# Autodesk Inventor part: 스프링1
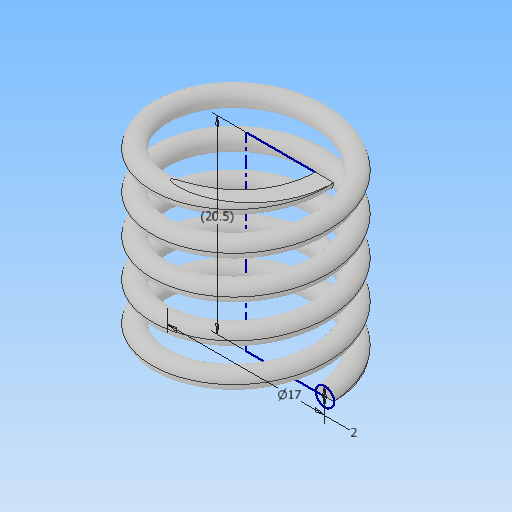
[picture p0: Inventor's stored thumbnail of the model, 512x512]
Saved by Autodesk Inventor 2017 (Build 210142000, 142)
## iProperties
Part Number: 스프링1
Material: 일반
Document SubType Name: Modeling
Designer: MRC
Density: 1 g/cm^3
Appearance: 기본값
Mass: 0.821961 g
Surface Area: 16.7185 cm^2
Volume: 0.821961 cm^3
Author: MRC
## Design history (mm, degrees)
sketch "스케치1"
  geometry: L1 (0, 0)-(0, 20.5); L2 (0, 0)-(8.5, 0); L3 (0, 20.5)-(7.5, 20.5); C1 r 1 at (8.5, 0)
  constraints: 6 end point, 2 horizontal, 1 centre point, 1 coincident, 1 vertical
  dimensions: "d0" = 20.5 distance of L1.start L1.end (derived); "d1" = 2 diameter of C1; "d2" = 17 diameter of L2.end L1
feature "코일1" sketch "스케치1" pitch "d3" = 10; turns "d5" = 5; dims "d4" = 20.5 (= d0), "d6" = 0, angle "d7" = 90 deg, angle "d8" = 90 deg, "d9" = 0, "d10" = 0
sketch "스케치2"
  geometry: L1 (20.5, 18.5)-(0, 18.5); L2 (0, 18.5)-(0, -18.5); L3 (0, -18.5)-(20.5, -18.5); L4 (20.5, -18.5)-(20.5, 18.5); 2 further points
  constraints: 8 end point, 2 parallel, 1 coincident, 1 horizontal, 1 midpoint, 1 perpendicular
  dimensions: "d11" = 37 distance of L3.end L1.start; "d12" = 20.5 distance of L2.end L3.end (= d0)
extrude "돌출1" sketch "스케치2" stored distance "d13" = 0; taper "d14" = 0 deg
node "솔리드1"
